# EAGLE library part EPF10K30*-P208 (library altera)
EPF10K30 FLEX 10K family
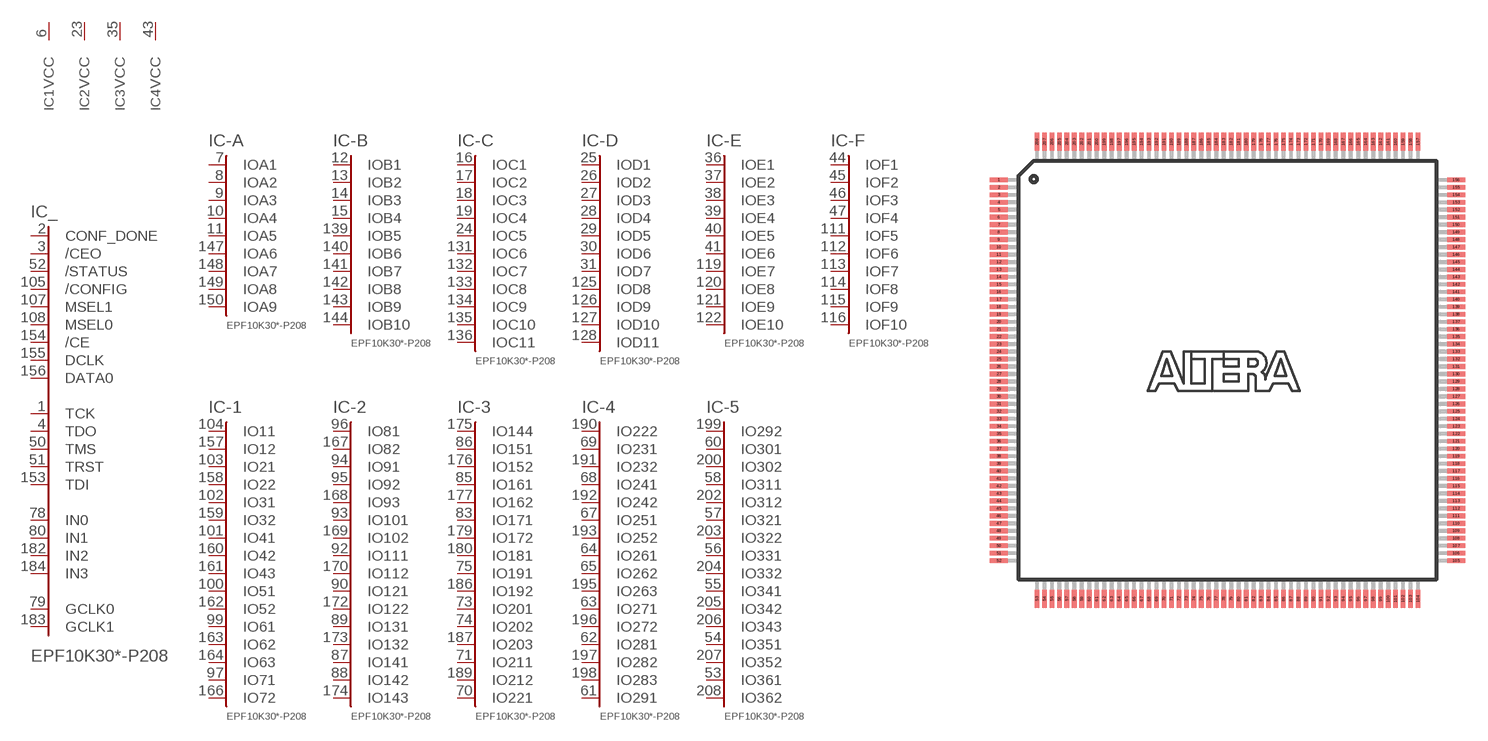
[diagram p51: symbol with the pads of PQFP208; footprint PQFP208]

Designator prefix IC; gates _=100R240C -A=A9 -B=B10 -C=C11 -D=D11 -E=E10 -F=F10 -1=72-30E -2=143-30E -3=221-30E -4=291-30E -5=362-30E 1=VCCINT 2=VCCINT 3=VCCINT 4=VCCINT 5=VCCINT 6=VCCINT 7=VCCINT 8=VCCINT 9=VCCINT 10=VCCINT 11=VCCINT 12=VCCINT 13=VCCIO 14=VCCIO 15=VCCIO 16=VCCIO 17=VCCIO 18=VCCIO 19=VCCIO 20=VCCIO 21=VCCIO 22=VCCIO 23=VCCIO 24=VCCIO 25=VCCIO 26=VCCIO 27=GND 28=GND 29=GND 30=GND 31=GND 32=GND 33=GND 34=GND 35=GND 36=GND 37=GND 38=GND 39=GND 40=GND 41=GND 42=GND 43=GND 44=GND 45=GND 46=GND 47=GND

## EPF10K30-P208 (MPN: EPF10K30EQC208-2N; OC_FARNELL: 1549382; OC_NEWARK: 51R8987), EPF10K30A-P208 (MPN: EPF10K30AQI208-3N; OC_FARNELL: unknown; OC_NEWARK: 51R8958)  [PQFP208]
1  _:TCK
2  _:CONF_DONE  in
3  _:/CEO  in
4  _:TDO
5  13:VCCIO  pwr
6  1:VCC  pwr
7  -A:IOA1
8  -A:IOA2
9  -A:IOA3
10  -A:IOA4
11  -A:IOA5
12  -B:IOB1
13  -B:IOB2
14  -B:IOB3
15  -B:IOB4
16  -C:IOC1
17  -C:IOC2
18  -C:IOC3
19  -C:IOC4
20  27:GND  pwr
21  28:GND  pwr
22  14:VCCIO  pwr
23  2:VCC  pwr
24  -C:IOC5
25  -D:IOD1
26  -D:IOD2
27  -D:IOD3
28  -D:IOD4
29  -D:IOD5
30  -D:IOD6
31  -D:IOD7
32  29:GND  pwr
33  30:GND  pwr
34  15:VCCIO  pwr
35  3:VCC  pwr
36  -E:IOE1
37  -E:IOE2
38  -E:IOE3
39  -E:IOE4
40  -E:IOE5
41  -E:IOE6
42  16:VCCIO  pwr
43  4:VCC  pwr
44  -F:IOF1
45  -F:IOF2
46  -F:IOF3
47  -F:IOF4
48  31:GND  pwr
49  32:GND  pwr
50  _:TMS
51  _:TRST
52  _:/STATUS  in
53  -5:IO361
54  -5:IO351
55  -5:IO341
56  -5:IO331
57  -5:IO321
58  -5:IO311
59  33:GND  pwr
60  -5:IO301
61  -4:IO291
62  -4:IO281
63  -4:IO271
64  -4:IO261
65  -4:IO262
66  17:VCCIO  pwr
67  -4:IO251
68  -4:IO241
69  -4:IO231
70  -3:IO221
71  -3:IO211
72  34:GND  pwr
73  -3:IO201
74  -3:IO202
75  -3:IO191
76  5:VCC  pwr
77  6:VCC  pwr
78  _:IN0  in
79  _:GCLK0  in
80  _:IN1  in
81  35:GND  pwr
82  36:GND  pwr
83  -3:IO171
84  18:VCCIO  pwr
85  -3:IO161
86  -3:IO151
87  -2:IO141
88  -2:IO142
89  -2:IO131
90  -2:IO121
91  37:GND  pwr
92  -2:IO111
93  -2:IO101
94  -2:IO91
95  -2:IO92
96  -2:IO81
97  -1:IO71
98  19:VCCIO  pwr
99  -1:IO61
100  -1:IO51
101  -1:IO41
102  -1:IO31
103  -1:IO21
104  -1:IO11
105  _:/CONFIG  in
106  7:VCC  pwr
107  _:MSEL1  in
108  _:MSEL0  in
109  8:VCC  pwr
110  20:VCCIO  pwr
111  -F:IOF5
112  -F:IOF6
113  -F:IOF7
114  -F:IOF8
115  -F:IOF9
116  -F:IOF10
117  9:VCC  pwr
118  21:VCCIO  pwr
119  -E:IOE7
120  -E:IOE8
121  -E:IOE9
122  -E:IOE10
123  38:GND  pwr
124  39:GND  pwr
125  -D:IOD8
126  -D:IOD9
127  -D:IOD10
128  -D:IOD11
129  40:GND  pwr
130  41:GND  pwr
131  -C:IOC6
132  -C:IOC7
133  -C:IOC8
134  -C:IOC9
135  -C:IOC10
136  -C:IOC11
137  10:VCC  pwr
138  22:VCCIO  pwr
139  -B:IOB5
140  -B:IOB6
141  -B:IOB7
142  -B:IOB8
143  -B:IOB9
144  -B:IOB10
145  11:VCC  pwr
146  23:VCCIO  pwr
147  -A:IOA6
148  -A:IOA7
149  -A:IOA8
150  -A:IOA9
151  42:GND  pwr
152  43:GND  pwr
153  _:TDI
154  _:/CE  in
155  _:DCLK  in
156  _:DATA0  in
157  -1:IO12
158  -1:IO22
159  -1:IO32
160  -1:IO42
161  -1:IO43
162  -1:IO52
163  -1:IO62
164  -1:IO63
165  24:VCCIO  pwr
166  -1:IO72
167  -2:IO82
168  -2:IO93
169  -2:IO102
170  -2:IO112
171  44:GND  pwr
172  -2:IO122
173  -2:IO132
174  -2:IO143
175  -3:IO144
176  -3:IO152
177  -3:IO162
178  25:VCCIO  pwr
179  -3:IO172
180  -3:IO181
181  12:VCC  pwr
182  _:IN2  in
183  _:GCLK1  in
184  _:IN3  in
185  45:GND  pwr
186  -3:IO192
187  -3:IO203
188  46:GND  pwr
189  -3:IO212
190  -4:IO222
191  -4:IO232
192  -4:IO242
193  -4:IO252
194  26:VCCIO  pwr
195  -4:IO263
196  -4:IO272
197  -4:IO282
198  -4:IO283
199  -5:IO292
200  -5:IO302
201  47:GND  pwr
202  -5:IO312
203  -5:IO322
204  -5:IO332
205  -5:IO342
206  -5:IO343
207  -5:IO352
208  -5:IO362

## Footprint PQFP208 (pad centres in mm)
Plastic Quad Flat Pack
smd 1.2 x 0.32: 1 -15.3,12.75; 2 -15.3,12.25; 3 -15.3,11.75; 4 -15.3,11.25; 5 -15.3,10.75; 6 -15.3,10.25; 7 -15.3,9.75; 8 -15.3,9.25; 9 -15.3,8.75; 10 -15.3,8.25; 11 -15.3,7.75; 12 -15.3,7.25; 13 -15.3,6.75; 14 -15.3,6.25; 15 -15.3,5.75; 16 -15.3,5.25; 17 -15.3,4.75; 18 -15.3,4.25; 19 -15.3,3.75; 20 -15.3,3.25; 21 -15.3,2.75; 22 -15.3,2.25; 23 -15.3,1.75; 24 -15.3,1.25; 25 -15.3,0.75; 26 -15.3,0.25; 27 -15.3,-0.25; 28 -15.3,-0.75; 29 -15.3,-1.25; 30 -15.3,-1.75; 31 -15.3,-2.25; 32 -15.3,-2.75; 33 -15.3,-3.25; 34 -15.3,-3.75; 35 -15.3,-4.25; 36 -15.3,-4.75; 37 -15.3,-5.25; 38 -15.3,-5.75; 39 -15.3,-6.25; 40 -15.3,-6.75; 41 -15.3,-7.25; 42 -15.3,-7.75; 43 -15.3,-8.25; 44 -15.3,-8.75; 45 -15.3,-9.25; 46 -15.3,-9.75; 47 -15.3,-10.25; 48 -15.3,-10.75; 49 -15.3,-11.25; 50 -15.3,-11.75; 51 -15.3,-12.25; 52 -15.3,-12.75; 105 15.3,-12.75; 106 15.3,-12.25; 107 15.3,-11.75; 108 15.3,-11.25; 109 15.3,-10.75; 110 15.3,-10.25; 111 15.3,-9.75; 112 15.3,-9.25; 113 15.3,-8.75; 114 15.3,-8.25; 115 15.3,-7.75; 116 15.3,-7.25; 117 15.3,-6.75; 118 15.3,-6.25; 119 15.3,-5.75; 120 15.3,-5.25; 121 15.3,-4.75; 122 15.3,-4.25; 123 15.3,-3.75; 124 15.3,-3.25; 125 15.3,-2.75; 126 15.3,-2.25; 127 15.3,-1.75; 128 15.3,-1.25; 129 15.3,-0.75; 130 15.3,-0.25; 131 15.3,0.25; 132 15.3,0.75; 133 15.3,1.25; 134 15.3,1.75; 135 15.3,2.25; 136 15.3,2.75; 137 15.3,3.25; 138 15.3,3.75; 139 15.3,4.25; 140 15.3,4.75; 141 15.3,5.25; 142 15.3,5.75; 143 15.3,6.25; 144 15.3,6.75; 145 15.3,7.25; 146 15.3,7.75; 147 15.3,8.25; 148 15.3,8.75; 149 15.3,9.25; 150 15.3,9.75; 151 15.3,10.25; 152 15.3,10.75; 153 15.3,11.25; 154 15.3,11.75; 155 15.3,12.25; 156 15.3,12.75
smd 0.32 x 1.2: 53 -12.75,-15.3; 54 -12.25,-15.3; 55 -11.75,-15.3; 56 -11.25,-15.3; 57 -10.75,-15.3; 58 -10.25,-15.3; 59 -9.75,-15.3; 60 -9.25,-15.3; 61 -8.75,-15.3; 62 -8.25,-15.3; 63 -7.75,-15.3; 64 -7.25,-15.3; 65 -6.75,-15.3; 66 -6.25,-15.3; 67 -5.75,-15.3; 68 -5.25,-15.3; 69 -4.75,-15.3; 70 -4.25,-15.3; 71 -3.75,-15.3; 72 -3.25,-15.3; 73 -2.75,-15.3; 74 -2.25,-15.3; 75 -1.75,-15.3; 76 -1.25,-15.3; 77 -0.75,-15.3; 78 -0.25,-15.3; 79 0.25,-15.3; 80 0.75,-15.3; 81 1.25,-15.3; 82 1.75,-15.3; 83 2.25,-15.3; 84 2.75,-15.3; 85 3.25,-15.3; 86 3.75,-15.3; 87 4.25,-15.3; 88 4.75,-15.3; 89 5.25,-15.3; 90 5.75,-15.3; 91 6.25,-15.3; 92 6.75,-15.3; 93 7.25,-15.3; 94 7.75,-15.3; 95 8.25,-15.3; 96 8.75,-15.3; 97 9.25,-15.3; 98 9.75,-15.3; 99 10.25,-15.3; 100 10.75,-15.3; 101 11.25,-15.3; 102 11.75,-15.3; 103 12.25,-15.3; 104 12.75,-15.3; 157 12.75,15.3; 158 12.25,15.3; 159 11.75,15.3; 160 11.25,15.3; 161 10.75,15.3; 162 10.25,15.3; 163 9.75,15.3; 164 9.25,15.3; 165 8.75,15.3; 166 8.25,15.3; 167 7.75,15.3; 168 7.25,15.3; 169 6.75,15.3; 170 6.25,15.3; 171 5.75,15.3; 172 5.25,15.3; 173 4.75,15.3; 174 4.25,15.3; 175 3.75,15.3; 176 3.25,15.3; 177 2.75,15.3; 178 2.25,15.3; 179 1.75,15.3; 180 1.25,15.3; 181 0.75,15.3; 182 0.25,15.3; 183 -0.25,15.3; 184 -0.75,15.3; 185 -1.25,15.3; 186 -1.75,15.3; 187 -2.25,15.3; 188 -2.75,15.3; 189 -3.25,15.3; 190 -3.75,15.3; 191 -4.25,15.3; 192 -4.75,15.3; 193 -5.25,15.3; 194 -5.75,15.3; 195 -6.25,15.3; 196 -6.75,15.3; 197 -7.25,15.3; 198 -7.75,15.3; 199 -8.25,15.3; 200 -8.75,15.3; 201 -9.25,15.3; 202 -9.75,15.3; 203 -10.25,15.3; 204 -10.75,15.3; 205 -11.25,15.3; 206 -11.75,15.3; 207 -12.25,15.3; 208 -12.75,15.3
